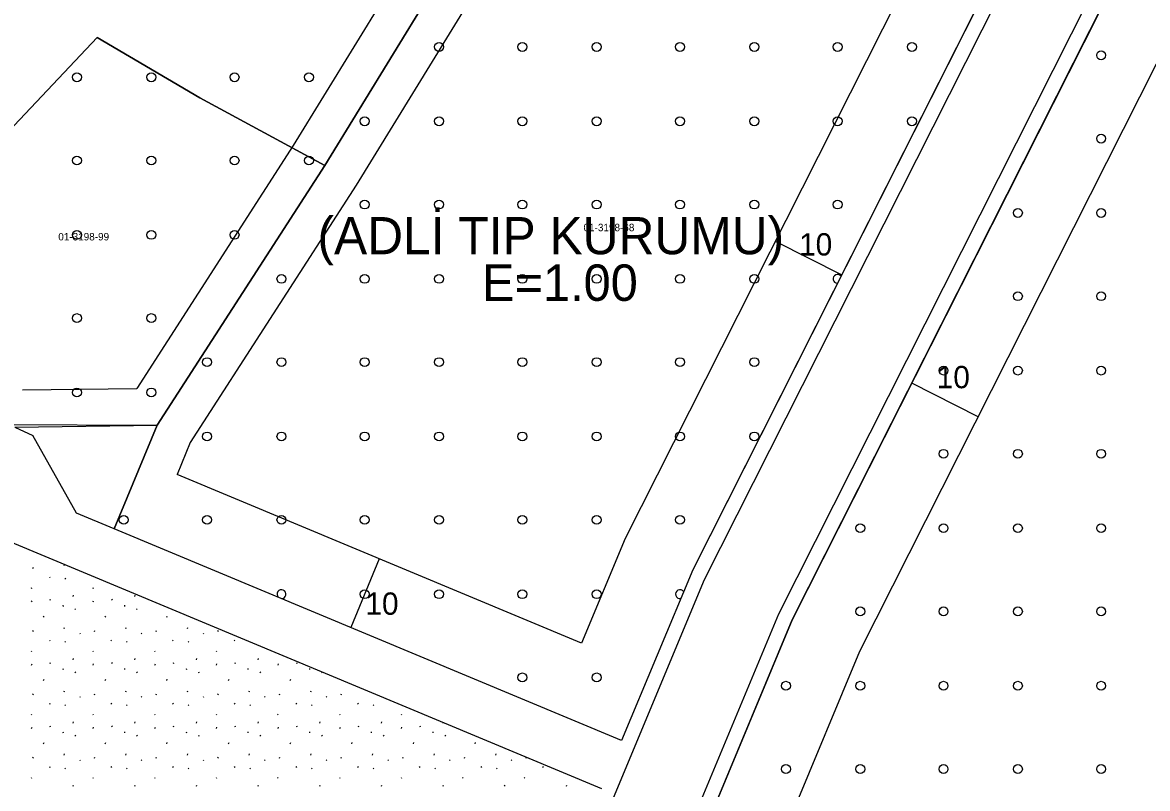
# Model space of a CAD drawing. Extents: x 419396 to 421519, y 4453567 to 4456767.
# Drawn here: x 420379 to 420530.3, y 4455291.9 to 4455394.9 of the extents above; entities that cross this region are included whole.
import ezdxf

# ---------------------------------------------------------------- set-up
doc = ezdxf.new("R2010")
doc.units = 0
for name, color, linetype in [('0_KADASTRO', 7, 'Continuous'), ('@PL', 7, 'Continuous'), ('ADAKENARI1000', 7, 'Continuous'), ('F_YAPI_YAKLAŞMA', 7, 'Continuous'), ('KALDIRIM', 7, 'Continuous'), ('Level 33', 7, 'Continuous'), ('Level 41', 7, 'Continuous'), ('SM_YAPILASMA', 7, 'Continuous')]:
    doc.layers.add(name, color=color, linetype=linetype)

msp = doc.modelspace()

# ---------------------------------------------------------------- linework, layer by layer
at = {"layer": '0_KADASTRO'}
for p, q in [((420419.68, 4455375.72), (420457.92, 4455437.99)), ((420345.22, 4455346.43), (420389.06, 4455392.9)), ((420389.06, 4455392.9), (420345.22, 4455346.43)), ((420389.06, 4455392.9), (420402.9, 4455384.78)), ((420402.9, 4455384.78), (420389.06, 4455392.9)), ((420402.9, 4455384.78), (420419.68, 4455375.72)), ((420419.68, 4455375.72), (420402.9, 4455384.78)), ((420397.16, 4455340.76), (420419.68, 4455375.72)), ((420357.81, 4455340.93), (420397.16, 4455340.76))]:
    msp.add_line(p, q, dxfattribs=at)
msp.add_lwpolyline([(420391.35, 4455326.84), (420397.16, 4455340.76), (420419.68, 4455375.72), (420457.92, 4455437.99), (420458.85, 4455454.77), (420525.87, 4455433.63), (420516.5, 4455415.06), (420469.18, 4455321.33), (420459.6, 4455298.36)], close=True, dxfattribs=at)
msp.add_lwpolyline([(420549.3, 4455446.81), (420540.37, 4455429.06), (420482.57, 4455314.58), (420453.85, 4455245.63), (420452.99, 4455236.3), (420611.77, 4455234.39), (420610.24, 4455191.26)], dxfattribs=at)
at = {"layer": 'ADAKENARI1000'}
for p, q in [((420457.92, 4455437.99), (420419.68, 4455375.72)), ((420482.57, 4455314.58), (420540.37, 4455429.06)), ((420516.5, 4455415.06), (420469.18, 4455321.33)), ((420419.68, 4455375.72), (420397.16, 4455340.76)), ((420378, 4455340.5), (420397.16, 4455340.76)), ((420397.16, 4455340.76), (420391.35, 4455326.84)), ((420397.16, 4455340.76), (420397.16, 4455340.76)), ((420378, 4455340.5), (420380.44, 4455339.4)), ((420386.3, 4455328.95), (420380.44, 4455339.4)), ((420391.35, 4455326.84), (420386.3, 4455328.95)), ((420459.6, 4455298.36), (420391.35, 4455326.84)), ((420376.87, 4455325.3), (420456.9, 4455291.9)), ((420469.18, 4455321.33), (420459.6, 4455298.36)), ((420453.85, 4455245.63), (420482.57, 4455314.58))]:
    msp.add_line(p, q, dxfattribs=at)
at = {"layer": 'F_YAPI_YAKLAŞMA'}
for p, q in [((420453, 4455439.53), (420415.45, 4455378.38)), ((420462.84, 4455436.45), (420423.91, 4455373.06)), ((420491.66, 4455310.39), (420549.3, 4455424.56)), ((420507.57, 4455419.56), (420460.09, 4455325.52)), ((420415.45, 4455378.38), (420394.41, 4455345.72)), ((420423.91, 4455373.06), (420401.6, 4455338.42)), ((420480.28, 4455365.51), (420489.21, 4455361)), ((420379.03, 4455345.51), (420394.41, 4455345.72)), ((420507.57, 4455341.91), (420498.65, 4455346.42)), ((420401.6, 4455338.42), (420399.82, 4455334.14)), ((420454.22, 4455311.44), (420399.82, 4455334.14)), ((420460.09, 4455325.52), (420454.22, 4455311.44)), ((420427.02, 4455322.79), (420423.17, 4455313.57)), ((420463.66, 4455243.19), (420491.66, 4455310.39))]:
    msp.add_line(p, q, dxfattribs=at)
at = {"layer": 'KALDIRIM'}
for p, q in [((420470.75, 4455320.01), (420528.73, 4455434.86)), ((420480.75, 4455315.41), (420538.55, 4455429.9)), ((420442.9, 4455253.16), (420470.75, 4455320.01)), ((420453.05, 4455248.93), (420480.75, 4455315.41))]:
    msp.add_line(p, q, dxfattribs=at)
at = {"layer": 'Level 33'}
for centre in [(420435.06, 4455391.65), (420446.26, 4455391.65), (420456.26, 4455391.65), (420467.46, 4455391.65), (420477.46, 4455391.65), (420488.66, 4455391.65), (420498.66, 4455391.65), (420524.11, 4455390.52), (420386.35, 4455387.57), (420396.35, 4455387.57), (420407.55, 4455387.57), (420417.55, 4455387.57), (420425.06, 4455381.65), (420435.06, 4455381.65), (420446.26, 4455381.65), (420456.26, 4455381.65), (420467.46, 4455381.65), (420477.46, 4455381.65), (420488.66, 4455381.65), (420498.66, 4455381.65), (420524.11, 4455379.32), (420386.35, 4455376.37), (420396.35, 4455376.37), (420407.55, 4455376.37), (420417.55, 4455376.37), (420425.06, 4455370.45), (420435.06, 4455370.45), (420446.26, 4455370.45), (420456.26, 4455370.45), (420467.46, 4455370.45), (420477.46, 4455370.45), (420488.66, 4455370.45), (420512.91, 4455369.32), (420524.11, 4455369.32), (420386.35, 4455366.37), (420396.35, 4455366.37), (420407.55, 4455366.37), (420413.86, 4455360.45), (420425.06, 4455360.45), (420435.06, 4455360.45), (420446.26, 4455360.45), (420456.26, 4455360.45), (420467.46, 4455360.45), (420477.46, 4455360.45), (420512.91, 4455358.12), (420524.11, 4455358.12), (420386.35, 4455355.17), (420396.35, 4455355.17), (420403.86, 4455349.25), (420413.86, 4455349.25), (420425.06, 4455349.25), (420435.06, 4455349.25), (420446.26, 4455349.25), (420456.26, 4455349.25), (420467.46, 4455349.25), (420477.46, 4455349.25), (420502.91, 4455348.12), (420512.91, 4455348.12), (420524.11, 4455348.12), (420386.35, 4455345.17), (420396.35, 4455345.17), (420403.86, 4455339.25), (420413.86, 4455339.25), (420425.06, 4455339.25), (420435.06, 4455339.25), (420446.26, 4455339.25), (420456.26, 4455339.25), (420467.46, 4455339.25), (420477.46, 4455339.25), (420502.91, 4455336.92), (420512.91, 4455336.92), (420524.11, 4455336.92), (420392.65, 4455328.04), (420403.86, 4455328.04), (420413.86, 4455328.04), (420425.06, 4455328.04), (420435.06, 4455328.04), (420446.26, 4455328.04), (420456.26, 4455328.04), (420467.46, 4455328.04), (420491.71, 4455326.92), (420502.91, 4455326.92), (420512.91, 4455326.92), (420524.11, 4455326.92), (420425.06, 4455318.04), (420435.06, 4455318.04), (420446.26, 4455318.04), (420456.26, 4455318.04), (420491.71, 4455315.72), (420502.91, 4455315.72), (420512.91, 4455315.72), (420524.11, 4455315.72), (420446.26, 4455306.84), (420456.26, 4455306.84), (420481.71, 4455305.72), (420491.71, 4455305.72), (420502.91, 4455305.72), (420512.91, 4455305.72), (420524.11, 4455305.72), (420481.71, 4455294.52), (420491.71, 4455294.52), (420502.91, 4455294.52), (420512.91, 4455294.52), (420524.11, 4455294.52)]:
    msp.add_circle(centre, 0.6, dxfattribs=at)
for centre, start, end in [((420488.66, 4455360.45), 39.8419, 266.5864), ((420413.86, 4455318.04), 271.3079, 223.3934), ((420467.46, 4455318.04), 34.7803, 279.9216)]:
    msp.add_arc(centre, 0.6, start, end, dxfattribs=at)
at = {"layer": 'Level 41'}
for p, q in [((420380.42, 4455321.51), (420380.49, 4455321.67)), ((420384.63, 4455321.92), (420384.68, 4455322.04)), ((420382.64, 4455320.38), (420382.71, 4455320.27)), ((420384.74, 4455320.18), (420384.81, 4455320.08)), ((420380.18, 4455318.92), (420380.25, 4455318.82)), ((420385.83, 4455317.73), (420385.9, 4455317.89)), ((420388.47, 4455318.92), (420388.54, 4455318.82)), ((420394.13, 4455317.73), (420394.2, 4455317.89)), ((420380.24, 4455317), (420380.31, 4455317.16)), ((420382.7, 4455317.35), (420382.77, 4455317.24)), ((420384.46, 4455316.56), (420384.48, 4455316.4)), ((420388.53, 4455317), (420388.6, 4455317.16)), ((420391, 4455317.35), (420391.07, 4455317.24)), ((420392.75, 4455316.56), (420392.77, 4455316.4)), ((420381.85, 4455314.94), (420381.93, 4455315.1)), ((420386.09, 4455316.09), (420386.16, 4455315.98)), ((420390.15, 4455314.94), (420390.22, 4455315.1)), ((420394.38, 4455316.09), (420394.45, 4455315.98)), ((420398.44, 4455314.94), (420398.51, 4455315.1)), ((420384.63, 4455313.41), (420384.7, 4455313.57)), ((420392.92, 4455313.41), (420392.99, 4455313.57)), ((420401.21, 4455313.41), (420401.28, 4455313.57)), ((420380.42, 4455313), (420380.49, 4455313.16)), ((420382.64, 4455311.87), (420382.71, 4455311.76)), ((420386.72, 4455312.8), (420386.79, 4455312.69)), ((420388.71, 4455313), (420388.78, 4455313.16)), ((420390.93, 4455311.87), (420391, 4455311.76)), ((420395.01, 4455312.8), (420395.09, 4455312.69)), ((420397, 4455313), (420397.07, 4455313.16)), ((420399.22, 4455311.87), (420399.29, 4455311.76)), ((420403.31, 4455312.8), (420403.38, 4455312.69)), ((420405.3, 4455313), (420405.37, 4455313.16)), ((420407.52, 4455311.87), (420407.59, 4455311.76)), ((420380.18, 4455310.41), (420380.25, 4455310.31)), ((420384.74, 4455311.67), (420384.81, 4455311.57)), ((420388.47, 4455310.41), (420388.54, 4455310.31)), ((420393.03, 4455311.67), (420393.1, 4455311.57)), ((420396.77, 4455310.41), (420396.84, 4455310.31)), ((420401.32, 4455311.67), (420401.39, 4455311.57)), ((420405.06, 4455310.41), (420405.13, 4455310.31)), ((420409.65, 4455311.62), (420409.69, 4455311.57)), ((420382.7, 4455308.84), (420382.77, 4455308.73)), ((420385.83, 4455309.22), (420385.9, 4455309.38)), ((420391, 4455308.84), (420391.07, 4455308.73)), ((420394.13, 4455309.22), (420394.2, 4455309.38)), ((420399.29, 4455308.84), (420399.36, 4455308.73)), ((420402.42, 4455309.22), (420402.49, 4455309.38)), ((420407.58, 4455308.84), (420407.65, 4455308.73)), ((420410.71, 4455309.22), (420410.78, 4455309.38)), ((420415.88, 4455308.84), (420415.95, 4455308.73)), ((420380.24, 4455308.49), (420380.31, 4455308.65)), ((420384.46, 4455308.05), (420384.48, 4455307.89)), ((420386.09, 4455307.58), (420386.16, 4455307.47)), ((420388.53, 4455308.49), (420388.6, 4455308.65)), ((420392.75, 4455308.05), (420392.77, 4455307.89)), ((420394.38, 4455307.58), (420394.45, 4455307.47)), ((420396.82, 4455308.49), (420396.9, 4455308.65)), ((420401.05, 4455308.05), (420401.07, 4455307.89)), ((420402.68, 4455307.58), (420402.75, 4455307.47)), ((420405.12, 4455308.49), (420405.19, 4455308.65)), ((420409.34, 4455308.05), (420409.36, 4455307.89)), ((420410.97, 4455307.58), (420411.04, 4455307.47)), ((420413.41, 4455308.49), (420413.48, 4455308.65)), ((420417.63, 4455308.05), (420417.65, 4455307.89)), ((420419.26, 4455307.58), (420419.33, 4455307.47)), ((420381.85, 4455306.43), (420381.93, 4455306.59)), ((420390.15, 4455306.43), (420390.22, 4455306.59)), ((420398.44, 4455306.43), (420398.51, 4455306.59)), ((420406.73, 4455306.43), (420406.81, 4455306.59)), ((420415.03, 4455306.43), (420415.1, 4455306.59)), ((420380.42, 4455304.49), (420380.49, 4455304.65)), ((420384.63, 4455304.9), (420384.7, 4455305.06)), ((420386.72, 4455304.29), (420386.79, 4455304.18)), ((420388.71, 4455304.49), (420388.78, 4455304.65)), ((420392.92, 4455304.9), (420392.99, 4455305.06)), ((420395.01, 4455304.29), (420395.09, 4455304.18)), ((420397, 4455304.49), (420397.07, 4455304.65)), ((420401.21, 4455304.9), (420401.28, 4455305.06)), ((420403.31, 4455304.29), (420403.38, 4455304.18)), ((420405.3, 4455304.49), (420405.37, 4455304.65)), ((420409.51, 4455304.9), (420409.58, 4455305.06)), ((420411.6, 4455304.29), (420411.67, 4455304.18)), ((420413.59, 4455304.49), (420413.66, 4455304.65)), ((420417.8, 4455304.9), (420417.87, 4455305.06)), ((420419.89, 4455304.29), (420419.96, 4455304.18)), ((420421.88, 4455304.49), (420421.95, 4455304.65)), ((420382.64, 4455303.36), (420382.71, 4455303.25)), ((420384.74, 4455303.16), (420384.81, 4455303.06)), ((420390.93, 4455303.36), (420391, 4455303.25)), ((420393.03, 4455303.16), (420393.1, 4455303.06)), ((420399.22, 4455303.36), (420399.29, 4455303.25)), ((420401.32, 4455303.16), (420401.39, 4455303.06)), ((420407.52, 4455303.36), (420407.59, 4455303.25)), ((420409.61, 4455303.16), (420409.69, 4455303.06)), ((420415.81, 4455303.36), (420415.88, 4455303.25)), ((420417.91, 4455303.16), (420417.98, 4455303.06)), ((420424.1, 4455303.36), (420424.17, 4455303.25)), ((420426.2, 4455303.16), (420426.27, 4455303.06)), ((420380.18, 4455301.9), (420380.25, 4455301.8)), ((420388.47, 4455301.9), (420388.54, 4455301.8)), ((420396.77, 4455301.9), (420396.84, 4455301.8)), ((420405.06, 4455301.9), (420405.13, 4455301.8)), ((420413.35, 4455301.9), (420413.42, 4455301.8)), ((420421.65, 4455301.9), (420421.72, 4455301.8)), ((420429.94, 4455301.9), (420430.01, 4455301.8)), ((420380.24, 4455299.98), (420380.31, 4455300.14)), ((420382.7, 4455300.33), (420382.77, 4455300.22)), ((420385.83, 4455300.71), (420385.9, 4455300.87)), ((420388.53, 4455299.98), (420388.6, 4455300.14)), ((420391, 4455300.33), (420391.07, 4455300.22)), ((420394.13, 4455300.71), (420394.2, 4455300.87)), ((420396.82, 4455299.98), (420396.9, 4455300.14)), ((420399.29, 4455300.33), (420399.36, 4455300.22)), ((420402.42, 4455300.71), (420402.49, 4455300.87)), ((420405.12, 4455299.98), (420405.19, 4455300.14)), ((420407.58, 4455300.33), (420407.65, 4455300.22)), ((420410.71, 4455300.71), (420410.78, 4455300.87)), ((420413.41, 4455299.98), (420413.48, 4455300.14)), ((420415.88, 4455300.33), (420415.95, 4455300.22)), ((420419, 4455300.71), (420419.08, 4455300.87)), ((420421.7, 4455299.98), (420421.78, 4455300.14)), ((420424.17, 4455300.33), (420424.24, 4455300.22)), ((420427.3, 4455300.71), (420427.37, 4455300.87)), ((420430, 4455299.98), (420430.07, 4455300.14)), ((420432.46, 4455300.33), (420432.53, 4455300.22)), ((420435.59, 4455300.71), (420435.62, 4455300.78)), ((420384.46, 4455299.54), (420384.48, 4455299.38)), ((420386.09, 4455299.07), (420386.16, 4455298.96)), ((420392.75, 4455299.54), (420392.77, 4455299.38)), ((420394.38, 4455299.07), (420394.45, 4455298.96)), ((420401.05, 4455299.54), (420401.07, 4455299.38)), ((420402.68, 4455299.07), (420402.75, 4455298.96)), ((420409.34, 4455299.54), (420409.36, 4455299.38)), ((420410.97, 4455299.07), (420411.04, 4455298.96)), ((420417.63, 4455299.54), (420417.65, 4455299.38)), ((420419.26, 4455299.07), (420419.33, 4455298.96)), ((420425.93, 4455299.54), (420425.94, 4455299.38)), ((420427.56, 4455299.07), (420427.63, 4455298.96)), ((420434.22, 4455299.54), (420434.24, 4455299.38)), ((420435.85, 4455299.07), (420435.92, 4455298.96)), ((420381.85, 4455297.92), (420381.93, 4455298.08)), ((420390.15, 4455297.92), (420390.22, 4455298.08)), ((420398.44, 4455297.92), (420398.51, 4455298.08)), ((420406.73, 4455297.92), (420406.81, 4455298.08)), ((420415.03, 4455297.92), (420415.1, 4455298.08)), ((420423.32, 4455297.92), (420423.39, 4455298.08)), ((420431.61, 4455297.92), (420431.68, 4455298.08)), ((420439.91, 4455297.92), (420439.98, 4455298.08)), ((420380.42, 4455295.98), (420380.49, 4455296.14)), ((420384.63, 4455296.39), (420384.7, 4455296.55)), ((420386.72, 4455295.78), (420386.79, 4455295.67)), ((420388.71, 4455295.98), (420388.78, 4455296.14)), ((420392.92, 4455296.39), (420392.99, 4455296.55)), ((420395.01, 4455295.78), (420395.09, 4455295.67)), ((420397, 4455295.98), (420397.07, 4455296.14)), ((420401.21, 4455296.39), (420401.28, 4455296.55)), ((420403.31, 4455295.78), (420403.38, 4455295.67)), ((420405.3, 4455295.98), (420405.37, 4455296.14)), ((420409.51, 4455296.39), (420409.58, 4455296.55)), ((420411.6, 4455295.78), (420411.67, 4455295.67)), ((420413.59, 4455295.98), (420413.66, 4455296.14)), ((420417.8, 4455296.39), (420417.87, 4455296.55)), ((420419.89, 4455295.78), (420419.96, 4455295.67)), ((420421.88, 4455295.98), (420421.95, 4455296.14)), ((420426.09, 4455296.39), (420426.16, 4455296.55)), ((420428.19, 4455295.78), (420428.26, 4455295.67)), ((420430.17, 4455295.98), (420430.25, 4455296.14)), ((420434.38, 4455296.39), (420434.45, 4455296.55)), ((420436.48, 4455295.78), (420436.55, 4455295.67)), ((420438.47, 4455295.98), (420438.54, 4455296.14)), ((420442.68, 4455296.39), (420442.75, 4455296.55)), ((420444.77, 4455295.78), (420444.84, 4455295.67)), ((420446.76, 4455295.98), (420446.82, 4455296.11)), ((420382.64, 4455294.85), (420382.71, 4455294.74)), ((420384.74, 4455294.65), (420384.81, 4455294.55)), ((420390.93, 4455294.85), (420391, 4455294.74)), ((420393.03, 4455294.65), (420393.1, 4455294.55)), ((420399.22, 4455294.85), (420399.29, 4455294.74)), ((420401.32, 4455294.65), (420401.39, 4455294.55)), ((420407.52, 4455294.85), (420407.59, 4455294.74)), ((420409.61, 4455294.65), (420409.69, 4455294.55)), ((420415.81, 4455294.85), (420415.88, 4455294.74)), ((420417.91, 4455294.65), (420417.98, 4455294.55)), ((420424.1, 4455294.85), (420424.17, 4455294.74)), ((420426.2, 4455294.65), (420426.27, 4455294.55)), ((420432.39, 4455294.85), (420432.47, 4455294.74)), ((420434.49, 4455294.65), (420434.56, 4455294.55)), ((420440.69, 4455294.85), (420440.76, 4455294.74)), ((420442.79, 4455294.65), (420442.86, 4455294.55)), ((420448.98, 4455294.85), (420449.05, 4455294.74)), ((420380.18, 4455293.39), (420380.25, 4455293.29)), ((420385.83, 4455292.2), (420385.9, 4455292.36)), ((420388.47, 4455293.39), (420388.54, 4455293.29)), ((420394.13, 4455292.2), (420394.2, 4455292.36)), ((420396.77, 4455293.39), (420396.84, 4455293.29)), ((420402.42, 4455292.2), (420402.49, 4455292.36)), ((420405.06, 4455293.39), (420405.13, 4455293.29)), ((420410.71, 4455292.2), (420410.78, 4455292.36)), ((420413.35, 4455293.39), (420413.42, 4455293.29)), ((420419, 4455292.2), (420419.08, 4455292.36)), ((420421.65, 4455293.39), (420421.72, 4455293.29)), ((420427.3, 4455292.2), (420427.37, 4455292.36)), ((420429.94, 4455293.39), (420430.01, 4455293.29)), ((420435.59, 4455292.2), (420435.66, 4455292.36)), ((420438.23, 4455293.39), (420438.3, 4455293.29)), ((420443.88, 4455292.2), (420443.95, 4455292.36)), ((420446.52, 4455293.39), (420446.6, 4455293.29)), ((420452.18, 4455292.2), (420452.25, 4455292.36))]:
    msp.add_line(p, q, dxfattribs=at)

# ---------------------------------------------------------------- texts
at = {"layer": '0_KADASTRO'}
for s, p in [('01-3198-68', (420454.49, 4455366.86)), ('01-3198-99', (420383.84, 4455365.62))]:
    msp.add_text(s, height=1, dxfattribs=at).set_placement(p)
at = {"layer": '@PL'}
msp.add_text('E=1.00', height=4.9, dxfattribs=at).set_placement((420440.84, 4455357.49))
at = {"layer": 'F_YAPI_YAKLAŞMA'}
for p in [(420483.48, 4455363.59), (420501.99, 4455345.74), (420425.15, 4455315.27)]:
    msp.add_text('10', height=3, dxfattribs=at).set_placement(p)
at = {"layer": 'SM_YAPILASMA'}
msp.add_text('(ADLİ TIP KURUMU)', height=5, dxfattribs=at).set_placement((420418.7, 4455363.76))

doc.saveas('drawing.dxf')
